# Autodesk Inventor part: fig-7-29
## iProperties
Shininess: 77.0
Length Units: 11269
Angle Units: 11279
Time Units: 11290
Mass Units: 11283
Length Display Precision: 3
Angle Display Precision: 2
Created: 2002-01
Part Number: fig-7-29
Document SubType Name: Modeling
Designer: CADSoft
Density: 0.0
Volumn: 0.0
Area: 0.0
PropertySet Name: Model Information
Control State: 0
Master: False
Checked Out: False
Author: CADSoft
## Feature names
1. Extrusion2
2. Coil6
